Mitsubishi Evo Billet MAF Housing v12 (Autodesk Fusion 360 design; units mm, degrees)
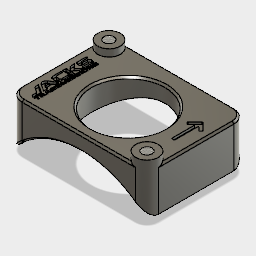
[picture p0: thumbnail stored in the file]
sketch "Sketch1" plane through (0, 0, 0) normal (0, 1, 0) x axis (1, 0, 0)
  line L1 (-30.23, -19.93) -> (-30.23, 17.3568)
  line L2 (23.0406, -19.93) -> (-30.23, -19.93)
  line L3 (27.7906, -14.4845) -> (27.7906, -15.18)
  line L4 (27.7906, 22.1068) -> (27.7906, -15.18)
  line L5 (-25.48, 22.1068) -> (27.7906, 22.1068)
  line L6 (23.0406, 17.3568) -> (-25.48, 17.3568)
  line L7 (23.0406, -15.18) -> (23.0406, 17.3568)
  line L8 (-25.48, -15.18) -> (23.0406, -15.18)
  line L9 (-25.48, 17.3568) -> (-25.48, -15.18)
  circle C1 centre (0, 0) radius 15.43
  circle C2 centre (-25.48, 17.3568) radius 4.75
  circle C3 centre (23.0406, -15.18) radius 4.75
  circle C4 centre (-25.48, 17.3568) radius 2
  circle C5 centre (23.0406, -15.18) radius 2
  point P2 (0, 0)
  point P7 (-25.48, 17.3568)
  point P8 (23.0406, -15.18)
  point P1 (0, 0)
  dimension "d1" diameter C1 = 30.86
  dimension "d5" diameter C2 = 9.5
  dimension "d6" diameter C3 = 9.5
  dimension "d8" distance P2 P7 = 30.83 (= "20.18 mm + 10.65 mm")
  dimension "d13" distance P7 P8 = 58.42
  dimension "d14" distance P1 L1 = 30.23 (= "15.43 mm + 14.8 mm")
  dimension "d15" distance P1 L2 = 19.93 (= "15.43 mm + 4.5 mm")
  dimension "d28" diameter C4 = 4
  dimension "d29" diameter C5 = 4
extrude "Extrude1" new body sketch "Sketch1" profile of C1 L1 L2 L3 L4 L5 C2 C3 against normal blind 25
extrude "Extrude2" sketch "Sketch1" profile of C2 C3 blind 3
sketch "Sketch2" plane through (0, 0, 19.93) normal (0, 0, 1) x axis (1, 0, 0)
  line L1 (-30.23, 0) -> (23.0406, 0)
  line L2 (-30.23, -25) -> (-30.23, 0)
  line L3 (23.0406, -25) -> (-30.23, -25)
  line L4 (23.0406, 0) -> (23.0406, -25)
  line L5 (0, -44.6) -> (0, -6.5)
  line L6 (0, -44.6) -> (0, 0)
  circle C1 centre (0, -44.6) radius 38.1
  point P1 (0, 0)
  point P7 (0, -6.5)
  dimension "d22" distance P1 P7 = 6.5
  dimension "d23" diameter C1 = 76.2
extrude "Extrude3" sketch "Sketch2" profile of L2 L3 L4 C1 L6 blind -45
fillet "Fillet1" radius 5.5
chamfer "Chamfer1" distance 0.75
extrude "Extrude4" cut sketch "Sketch1" profile of C4 C5 along normal blind 3 and against normal blind 7
thread "Thread1"
sketch "LOGO" plane through (-23.1778, 0, 9.19) normal (0, 1, 0) x axis (1, 0, 0)
  line L1 (-3.7315, -1.7189) -> (-0.5085, -3.7265)
  line L2 (-0.3, 8.4561) -> (-0.3, 9.9561)
  line L3 (-0.32, 1.8384) -> (-1.0479, 1.3958)
  line L4 (-3.1198, 15.6775) -> (-3.1198, 18.5091)
  line L5 (-3.7315, -3.1976) -> (-3.7315, -1.7189)
  line L6 (-2.6793, 15.4775) -> (-2.9198, 15.4775)
  line L7 (-2.4793, 17.7091) -> (-2.4793, 15.6775)
  line L8 (-0.32, 4.1561) -> (-0.32, 8)
  line L9 (-0.32, 3.3816) -> (-0.32, 1.8384)
  line L10 (-3.8, 11.8561) -> (-3.8, 13.5561)
  line L11 (-1.0814, 18.5091) -> (-1.6793, 18.5091)
  line L12 (-1.24, -6.8439) -> (-1.24, -5.152)
  line L13 (-1, 8) -> (-1, 5.4247)
  line L14 (-0.32, -7.4439) -> (-1.24, -6.8439)
  line L15 (-1.4104, -4.8244) -> (-3.7315, -3.1976)
  line L16 (-0.32, -4.066) -> (-0.32, -7.4439)
  line L17 (-0.32, -2.8663) -> (-3.1889, -1.0793)
  line L18 (-1.8, 0.9561) -> (-1.8, -0.4439)
  line L19 (-1.0479, -0.8439) -> (-0.32, -1.3209)
  line L20 (-0.3129, 13.5561) -> (-0.3129, 11.9561)
  line L21 (1.2453, 1.3146) -> (1.2453, 2.3761)
  line L22 (-1.8, -0.4439) -> (-3, 0.2561)
  line L23 (0.6349, 3.8561) -> (1.5, 3.8561)
  line L24 (-3.8, 9.9561) -> (-3.8, 8.4561)
  line L25 (1.5, -3.7439) -> (0.9937, -4.2999)
  line L26 (-3, 3.3561) -> (-1.12, 3.3561)
  line L27 (0.4742, -1.8254) -> (1.5, -1.2111)
  line L28 (0.2, 1.5995) -> (0.2, 2.9561)
  line L29 (1.5, 0.7083) -> (1.5, 0.2783)
  line L30 (-3.1743, 1.6459) -> (-0.32, 3.3816)
  line L31 (-2.1, 11.6561) -> (-0.3129, 13.5561)
  line L32 (-3.8, 7.9561) -> (-3.8, 4.1561)
  line L33 (0.4473, -7.4439) -> (0.2, -7.4439)
  line L34 (0.2, -5.5439) -> (1.501, -5.5439)
  line L35 (0.2, -5.8439) -> (0.4473, -5.8439)
  line L36 (-2.2478, 10.157) -> (-3.8, 11.8561)
  line L37 (1.5, 3.8561) -> (1.5, 3.3561)
  line L38 (1.4028, 0.1067) -> (0.5772, -0.3877)
  line L39 (-3.1198, 18.5091) -> (-3.8, 18.5024)
  line L40 (-0.32, 8) -> (-1, 8)
  line L41 (-1.6, 4.8247) -> (-2.542, 4.8247)
  line L42 (-0.2814, 13.9561) -> (-0.2814, 17.7091)
  line L43 (0.4473, -6.4439) -> (1.501, -6.4439)
  line L44 (-3.8, 18.5024) -> (-3.8, 14.6841)
  line L45 (-0.32, -1.3209) -> (-0.32, -2.8663)
  line L46 (1.501, -6.9088) -> (0.4473, -6.9088)
  line L47 (-3.142, 7.9561) -> (-3.8, 7.9561)
  line L48 (0.4473, -5.8439) -> (0.4473, -6.4439)
  line L49 (-1.0479, 1.3958) -> (-1.0479, -0.8439)
  line L50 (-3.8, 8.4561) -> (-0.3, 8.4561)
  line L51 (-1, 16.7989) -> (-1, 13.9561)
  line L52 (-0.3129, 11.9561) -> (-1.9524, 10.1572)
  line L53 (0.2, -4.1439) -> (0.2, -5.5439)
  line L54 (0.4473, -6.9088) -> (0.4473, -7.4439)
  line L55 (-3, 0.2561) -> (-1.8, 0.9561)
  line L56 (-3.142, 5.4247) -> (-3.142, 7.9561)
  line L57 (-1, 13.9561) -> (-0.2814, 13.9561)
  line L58 (-1.4905, 16.9989) -> (-1.2, 16.9989)
  line L59 (0.2972, -0.0857) -> (1.1072, 0.3994)
  line L60 (0.7, 1.2995) -> (0.5, 1.2995)
  line L61 (1.5, 3.3561) -> (0.4, 3.3561)
  line L62 (1.501, -6.4439) -> (1.501, -6.9088)
  line L63 (0.2, -7.4439) -> (0.2, -5.8439)
  line L64 (-1.6905, 14.6841) -> (-1.6905, 16.7989)
  line L65 (0.2, -0.7439) -> (0.2, -0.2572)
  line L66 (-0.3, 9.9561) -> (-3.8, 9.9561)
  line L67 (1.5, -3.5016) -> (0.4625, -2.8477)
  line L68 (-3.8, 13.5561) -> (-2.1, 11.6561)
  line L69 (-3, 13.8841) -> (-2.4905, 13.8841)
  line L70 (1, -2.1874) -> (1, -2.5408)
  line L71 (0.2007, 18.504) -> (0.4587, 18.504)
  line L72 (0.733, 1.8993) -> (0.733, 2.6561)
  line L73 (1.5, -2.9617) -> (1.5, -3.5016)
  line L74 (0.2, 2.9561) -> (0.4581, 2.9561)
  line L75 (0.2, 10.9977) -> (0.4581, 10.9977)
  line L76 (1.5, 1.3146) -> (1.2453, 1.3146)
  line L77 (0.5618, -3.7439) -> (0.6, -3.7439)
  line L78 (1.2453, 9.3561) -> (1.2453, 10.4177)
  line L79 (1.5, -1.7574) -> (1.2113, -1.9302)
  line L80 (1.5007, 18.204) -> (1.5007, 16.8625)
  line L81 (0.2, 5.2797) -> (0.2, 5.7561)
  line L82 (1, 2.3761) -> (1, 1.5995)
  line L83 (1.5, -0.9439) -> (0.4, -0.9439)
  line L84 (1.0337, 18.504) -> (1.2007, 18.504)
  line L85 (1.2459, 16.8625) -> (1.2459, 17.924)
  line L86 (1.5007, 16.8625) -> (1.2459, 16.8625)
  line L87 (0.2, 0.4737) -> (0.2, 0.9083)
  line L88 (1.5, 6.9561) -> (0.2, 6.9561)
  line L89 (0.6216, -2.3081) -> (0.9092, -2.1359)
  line L90 (1.5, 2.6561) -> (1.5, 1.3146)
  line L91 (1.033, 2.9561) -> (1.2, 2.9561)
  line L92 (0.2, 0.9083) -> (1.3, 0.9083)
  line L93 (0.5978, -0.462) -> (1.5, -0.462)
  line L94 (1.2113, -2.7797) -> (1.5, -2.9617)
  line L95 (0.5149, -4.2087) -> (0.74, -4.2087)
  line L96 (1.5, -1.2111) -> (1.5, -1.7574)
  line L97 (1.2113, -1.9302) -> (1.2113, -2.7797)
  line L98 (0.5381, 1.8193) -> (0.653, 1.8193)
  line L99 (1.5, 5.5052) -> (0.6446, 5.5052)
  line L100 (0.7015, 7.3331) -> (0.5015, 7.3331)
  line L101 (1.1653, 10.4977) -> (1.08, 10.4977)
  line L102 (0.7346, 7.9329) -> (0.7346, 8.6897)
  line L103 (1.0007, 17.924) -> (1.0007, 17.1474)
  line L104 (0.3106, 4.2114) -> (1.1284, 4.6203)
  line L105 (0.4587, 18.504) -> (0.4587, 17.4472)
  line L106 (0.7007, 16.8474) -> (0.5007, 16.8474)
  line L107 (0.4549, -4.9839) -> (0.4549, -4.2687)
  line L108 (0.4581, 2.9561) -> (0.4581, 1.8993)
  line L109 (1.501, -5.0439) -> (0.5149, -5.0439)
  line L110 (1.409, 4.447) -> (0.6131, 3.9296)
  line L111 (1.5, -0.462) -> (1.5, -0.9439)
  line L112 (0.8, -4.2687) -> (0.8, -4.7932)
  line L113 (0.9937, -4.2999) -> (0.9562, -4.0774)
  line L114 (1.0393, -4.8439) -> (1.5, -4.3439)
  line L115 (1.0866, 0.4737) -> (0.2, 0.4737)
  line L116 (1.501, -5.5439) -> (1.501, -5.0439)
  line L117 (0.908, -2.5916) -> (0.6205, -2.4103)
  line L118 (1.5, -4.3439) -> (1.5, -3.7439)
  line L119 (1.1653, 2.4561) -> (1.08, 2.4561)
  line L120 (0.5396, 7.8529) -> (0.6546, 7.8529)
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extrude "Extrude5" sketch "LOGO" blind -1
sketch "Sketch4" plane through (0, 0, 0) normal (0, 1, 0) x axis (-1, 0, 0)
  line L1 (22.9183, -21.3568) -> (-22.2906, -21.3568)
  line L2 (29.48, 14.43) -> (29.48, -14.7951)
  line L3 (-20.4789, 19.18) -> (24.73, 19.18)
  line L4 (-27.0406, -16.6068) -> (-27.0406, 12.6183)
  line L5 (22.9778, 16.6339) -> (22.7305, 16.6339)
  line L6 (22.9778, 15.0339) -> (22.9778, 16.6339)
  line L7 (22.7305, 15.0339) -> (22.9778, 15.0339)
  line L8 (22.7305, 15.6339) -> (22.7305, 15.0339)
  line L9 (21.6768, 15.6339) -> (22.7305, 15.6339)
  line L10 (21.6768, 16.0989) -> (21.6768, 15.6339)
  line L11 (22.7305, 16.0989) -> (21.6768, 16.0989)
  line L12 (22.7305, 16.6339) -> (22.7305, 16.0989)
  line L13 (22.9778, 6.2339) -> (22.9778, 7.5905)
  line L14 (22.7197, 6.2339) -> (22.9778, 6.2339)
  line L15 (22.7197, 7.2907) -> (22.7197, 6.2339)
  line L16 (22.5248, 7.3707) -> (22.6397, 7.3707)
  line L17 (22.4448, 6.5339) -> (22.4448, 7.2907)
  line L18 (21.9778, 6.2339) -> (22.1448, 6.2339)
  line L19 (21.6778, 7.8755) -> (21.6778, 6.5339)
  line L20 (21.9325, 7.8755) -> (21.6778, 7.8755)
  line L21 (21.9325, 6.8139) -> (21.9325, 7.8755)
  line L22 (22.0978, 6.7339) -> (22.0125, 6.7339)
  line L23 (22.1778, 7.5905) -> (22.1778, 6.8139)
  line L24 (22.6778, 7.8905) -> (22.4778, 7.8905)
  line L25 (22.9778, -1.8076) -> (22.9778, -0.451)
  line L26 (22.7197, -1.8076) -> (22.9778, -1.8076)
  line L27 (22.7197, -0.7508) -> (22.7197, -1.8076)
  line L28 (22.5248, -0.6708) -> (22.6397, -0.6708)
  line L29 (22.4448, -1.5076) -> (22.4448, -0.7508)
  line L30 (21.9778, -1.8076) -> (22.1448, -1.8076)
  line L31 (21.6778, -0.1661) -> (21.6778, -1.5076)
  line L32 (21.9325, -0.1661) -> (21.6778, -0.1661)
  line L33 (21.9325, -1.2276) -> (21.9325, -0.1661)
  line L34 (22.0978, -1.3076) -> (22.0125, -1.3076)
  line L35 (22.1778, -0.451) -> (22.1778, -1.2276)
  line L36 (22.6778, -0.151) -> (22.4778, -0.151)
  line L37 (22.7191, -9.314) -> (22.9772, -9.314)
  line L38 (22.7191, -8.2572) -> (22.7191, -9.314)
  line L39 (22.5241, -8.1772) -> (22.6391, -8.1772)
  line L40 (22.4441, -9.014) -> (22.4441, -8.2572)
  line L41 (21.9772, -9.314) -> (22.1441, -9.314)
  line L42 (21.6772, -7.6724) -> (21.6772, -9.014)
  line L43 (21.9319, -7.6724) -> (21.6772, -7.6724)
  line L44 (21.9319, -8.734) -> (21.9319, -7.6724)
  line L45 (22.0972, -8.814) -> (22.0119, -8.814)
  line L46 (22.1772, -7.9574) -> (22.1772, -8.734)
  line L47 (22.6772, -7.6574) -> (22.4772, -7.6574)
  line L48 (22.9772, -9.314) -> (22.9772, -7.9574)
  line L49 (26.9778, 0.7339) -> (23.4778, 0.7339)
  line L50 (26.9778, -0.7661) -> (26.9778, 0.7339)
  line L51 (23.4778, -0.7661) -> (26.9778, -0.7661)
  line L52 (23.4778, 0.7339) -> (23.4778, -0.7661)
  line L53 (26.9778, -4.3661) -> (26.9778, -2.6661)
  line L54 (25.2778, -2.4661) -> (26.9778, -4.3661)
  line L55 (23.4908, -4.3661) -> (25.2778, -2.4661)
  line L56 (23.4908, -2.7661) -> (23.4908, -4.3661)
  line L57 (25.1302, -0.9672) -> (23.4908, -2.7661)
  line L58 (26.9778, -2.6661) -> (25.4257, -0.967)
  line L59 (24.4178, 14.342) -> (24.4178, 16.0339)
  line L60 (26.9093, 12.3876) -> (24.5882, 14.0145)
  line L61 (26.9093, 10.9089) -> (26.9093, 12.3876)
  line L62 (23.6863, 12.9165) -> (26.9093, 10.9089)
  line L63 (23.4978, 16.6339) -> (23.4978, 13.256)
  line L64 (24.4178, 16.0339) -> (23.4978, 16.6339)
  line L65 (21.6778, -2.194) -> (21.6778, -2.7371)
  line L66 (22.9778, -2.194) -> (21.6778, -2.194)
  line L67 (22.9778, -2.7371) -> (22.9778, -2.194)
  line L68 (21.6778, -2.7371) -> (22.9778, -2.7371)
  line L69 (22.5332, 3.6848) -> (21.6778, 3.6848)
  line L70 (21.775, 4.2257) -> (22.5538, 3.7591)
  line L71 (21.6778, 4.5754) -> (21.6778, 4.3973)
  line L72 (22.5647, 5.2604) -> (21.7688, 4.7431)
  line L73 (21.6778, 5.3339) -> (22.5429, 5.3339)
  line L74 (21.6778, 5.8339) -> (21.6778, 5.3339)
  line L75 (22.7778, 5.8339) -> (21.6778, 5.8339)
  line L76 (22.9778, 5.1575) -> (22.9778, 5.6339)
  line L77 (22.0494, 4.5697) -> (22.8673, 4.9786)
  line L78 (22.8673, 4.0892) -> (22.0494, 4.4981)
  line L79 (22.9778, 3.4339) -> (22.9778, 3.9103)
  line L80 (21.6778, 3.2339) -> (22.7778, 3.2339)
  line L81 (21.6778, 3.6848) -> (21.6778, 3.2339)
  line L82 (22.1385, 14.0339) -> (21.6778, 13.5339)
  line L83 (22.3778, 13.4587) -> (22.3778, 13.9832)
  line L84 (22.6629, 13.3987) -> (22.4378, 13.3987)
  line L85 (22.7229, 14.1739) -> (22.7229, 13.4587)
  line L86 (21.6768, 14.2339) -> (22.6629, 14.2339)
  line L87 (21.6768, 14.7339) -> (21.6768, 14.2339)
  line L88 (22.9778, 14.7339) -> (21.6768, 14.7339)
  line L89 (22.9778, 13.3339) -> (22.9778, 14.7339)
  line L90 (22.1841, 13.4899) -> (22.2216, 13.2675)
  line L91 (21.6778, 12.9339) -> (22.1841, 13.4899)
  line L92 (21.6778, 13.5339) -> (21.6778, 12.9339)
  line L93 (22.9778, 8.7163) -> (22.0912, 8.7163)
  line L94 (22.9778, 8.2817) -> (22.9778, 8.7163)
  line L95 (21.8778, 8.2817) -> (22.9778, 8.2817)
  line L96 (21.6778, 8.9118) -> (21.6778, 8.4817)
  line L97 (22.6006, 9.5777) -> (21.7751, 9.0834)
  line L98 (21.6778, 9.6521) -> (22.58, 9.6521)
  line L99 (21.6778, 10.1339) -> (21.6778, 9.6521)
  line L100 (22.7778, 10.1339) -> (21.6778, 10.1339)
  line L101 (22.9778, 9.4473) -> (22.9778, 9.9339)
  line L102 (22.0706, 8.7906) -> (22.8806, 9.2757)
  line L103 (22.9763, 0.2003) -> (22.9763, 1.5569)
  line L104 (22.7182, 0.2003) -> (22.9763, 0.2003)
  line L105 (22.7182, 1.2571) -> (22.7182, 0.2003)
  line L106 (22.5232, 1.3371) -> (22.6382, 1.3371)
  line L107 (22.4432, 0.5003) -> (22.4432, 1.2571)
  line L108 (21.9763, 0.2003) -> (22.1432, 0.2003)
  line L109 (21.6763, 1.8419) -> (21.6763, 0.5003)
  line L110 (21.931, 1.8419) -> (21.6763, 1.8419)
  line L111 (21.931, 0.7803) -> (21.931, 1.8419)
  line L112 (22.0963, 0.7003) -> (22.011, 0.7003)
  line L113 (22.1763, 1.5569) -> (22.1763, 0.7803)
  line L114 (22.6763, 1.8569) -> (22.4763, 1.8569)
  line L115 (21.6714, -6.6194) -> (21.6714, -7.0495)
  line L116 (22.5942, -5.9535) -> (21.7687, -6.4478)
  line L117 (21.6714, -5.8791) -> (22.5736, -5.8791)
  line L118 (21.6714, -5.3973) -> (21.6714, -5.8791)
  line L119 (22.7714, -5.3973) -> (21.6714, -5.3973)
  line L120 (22.9714, -6.0839) -> (22.9714, -5.5973)
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  dimension "d36" angle = 45
  dimension "d37" angle = 45
extrude "Extrude6" sketch "Sketch4" blind -1
fillet "Fillet2" radius 0.3
sketch "Sketch5" plane through (0, 0, 0) normal (0, 1, 0) x axis (1, 0, 0)
  line L1 (44, -27) -> (-39, -27)
  line L2 (44, 32) -> (44, -27)
  line L3 (-39, 32) -> (44, 32)
  line L4 (-39, -27) -> (-39, 32)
